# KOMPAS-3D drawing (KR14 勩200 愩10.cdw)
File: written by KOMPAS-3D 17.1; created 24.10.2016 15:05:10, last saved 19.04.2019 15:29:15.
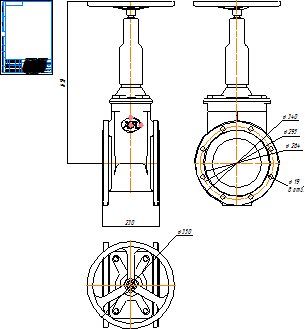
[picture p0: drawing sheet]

Sheet 1: A4, portrait

Title block, sheet 1: name: KR14 Ду200 Ру10; material: Внимание! Данный продукт является объектом авторского права ООО «Торговый Дом АДЛ». / Запрещается изменение, копирование, распространение / (в том числе путем копирования на другие сайты и ресурсы в Интернете) / или любое иное использование информации и объектов без предварительного / согласия правообладателя (ООО «Торговый Дом АДЛ»).; mass: 124,1; sheets: 1; organisation: ООО "Торговый дом АДЛ"; sheet format: A4; stored path: \\adlc.lan\data\АДЛ_ПКД\3D-модели\ADL production\Клиновые задвижки серии KR ГРАНАР\Клиновые задвижки KR14\kompas 2d\KR14 Ду200 Ру10.cdw

Views: Вид 1, Проекционный вид 2, Проекционный вид 3
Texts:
  Klimkovich
  ADL
Dimensions and other numbers on the sheet: 230; 651; 340; 295; 264; 19; 8 отв.; 350; 1:1; 1; 124,1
